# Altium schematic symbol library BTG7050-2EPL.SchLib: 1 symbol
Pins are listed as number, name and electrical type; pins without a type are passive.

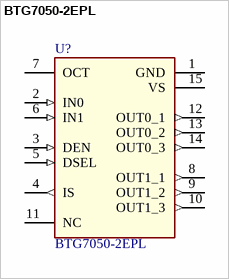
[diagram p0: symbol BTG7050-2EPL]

## BTG7050-2EPL
designator U?
PROFET Load Guard, Smart high-side power switch; Manufacturer: Infineon Technologies
pins: 1 GND (power) "Ground", 2 IN0 (in) "Input Channel 0", 3 DEN (in) "Diagnostic Enable", 4 IS (out) "SENSE current output", 5 DSEL (in) "Diagnosis Selection", 6 IN1 (in) "Input Channel 1", 7 OCT "Adjustable overcurrent threshold", 8 OUT1_1 (out) "Output 1", 9 OUT1_2 (out) "Output 2", 10 OUT1_3 (out) "Output 3", 11 NC "Not Connected", 12 OUT0_1 (out) "Output 1", 13 OUT0_2 (out) "Output 2", 14 OUT0_3 (out) "Output 3", 15 VS (power) "Supply Voltage"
